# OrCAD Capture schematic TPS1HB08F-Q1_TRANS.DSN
size E; title: TPS1HB08F-Q1: 40-V, 8-mOhm Single-Channel Smart; rev: 1.0; note: Datasheet: SLVSE16C     EVM: NA; note: High-Side Switch
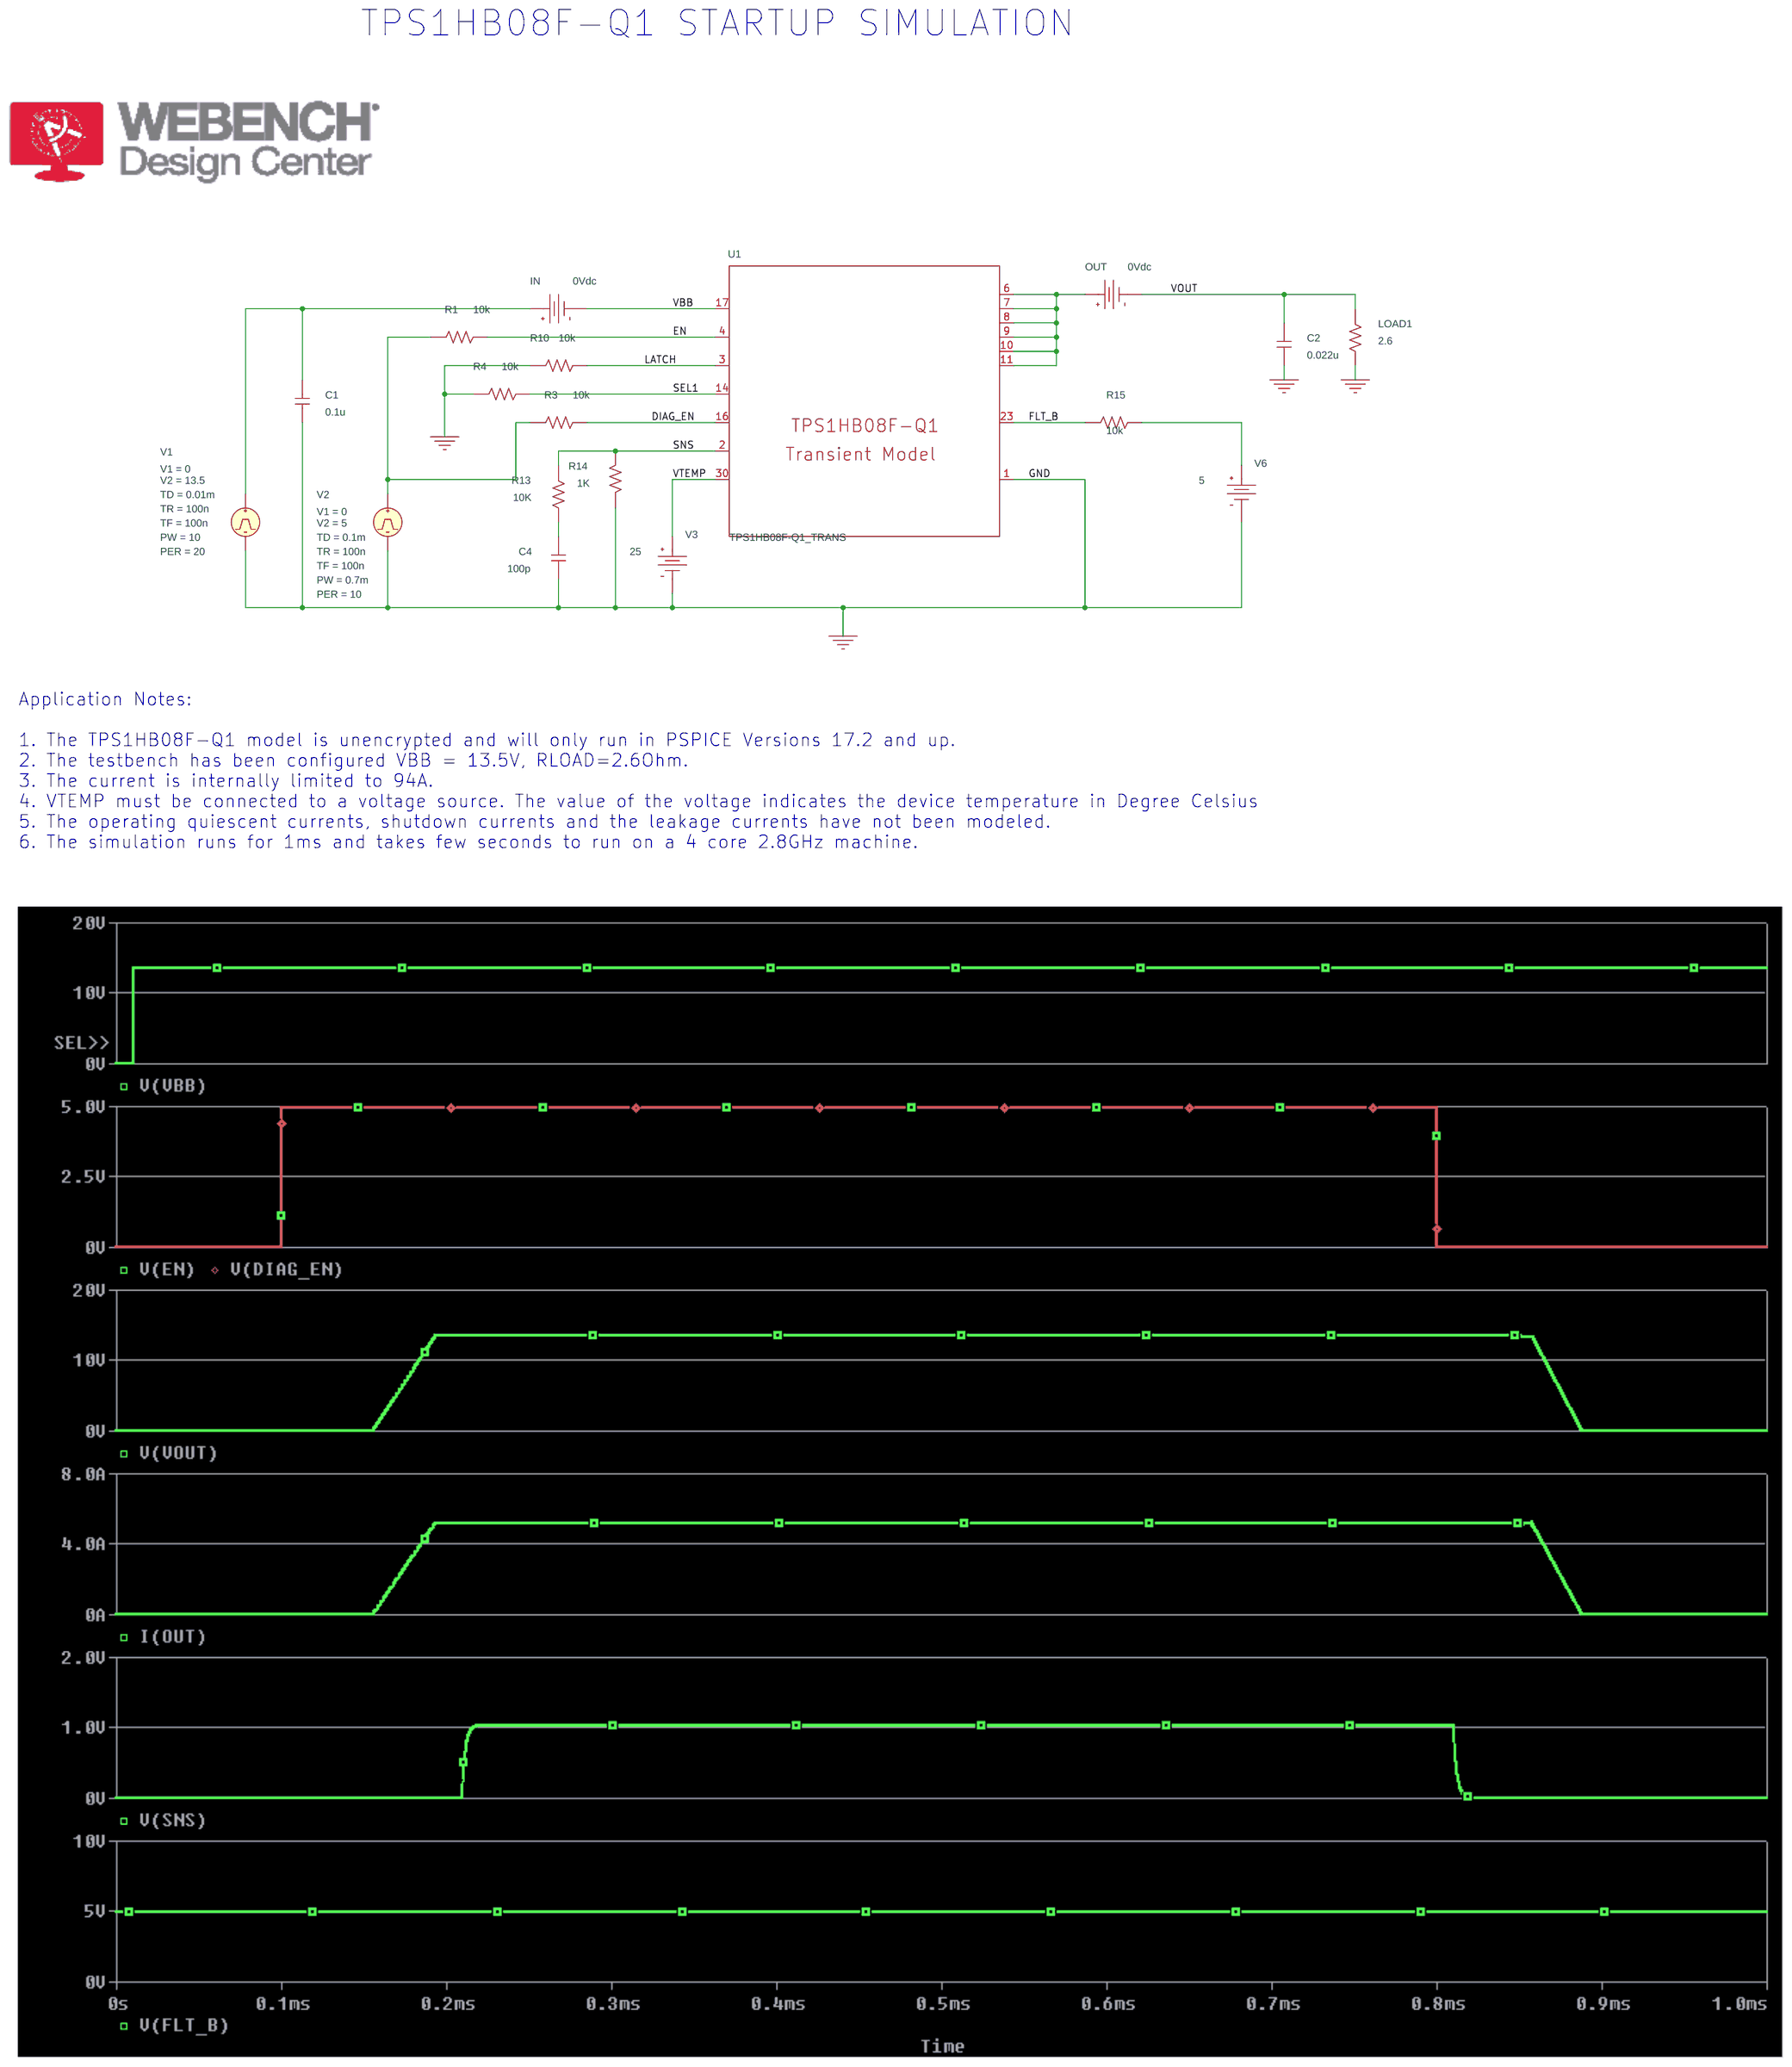
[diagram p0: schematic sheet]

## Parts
C1  0.1u  [RAD/CK05]
C2  0.022u  [RAD/CK05]
C4  100p  [RAD/CK05]
IN  VDC
LOAD1  2.6  [AX/RC05]
OUT  VDC
R1  10k  [AX/RC05]
R3  10k  [AX/RC05]
R4  10k  [AX/RC05]
R10  10k  [AX/RC05]
R13  10K  [AX/RC05]
R14  1K  [AX/RC05]
R15  10k  [AX/RC05]
U1  TPS1HB08F-Q1_TRANS  [PWP0016M_N]
V1  VPULSE
V2  VPULSE
V3  VDC
V6  VDC

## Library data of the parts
C1 C2 C4 = C
IN OUT = VDC: DC: 0Vdc
LOAD1 R1 R3 R4 R10 R13-R15 = R
U1 = TPS1HB08F-Q1_TRANS
V1 = VPULSE: PER: 20; PW: 10; TD: 0.01m; TF: 100n; TR: 100n; V1: 0; V2: 13.5
V2 = VPULSE: PER: 10; PW: 0.7m; TD: 0.1m; TF: 100n; TR: 100n; V1: 0; V2: 5
V3 = VDC: DC: 25
V6 = VDC: DC: 5

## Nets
0: C1.2 C2.2 C4.2 LOAD1.2 R4.1 R10.1 R14.1 U1.1(GND) V1.2(-) V2.2(-) V3.1(-) V6.1(-)
DIAG_EN: R3.2 U1.16(DIA_EN)
EN: R1.2 U1.4(EN)
FLT_B: R15.1 U1.23(FLT_B)
LATCH: R10.2 U1.3(LATCH)
SEL1: R4.2 U1.14(SEL1)
SNS: R13.1 R14.2 U1.2(SNS)
VBB: IN.1(-) U1.17(VBB)
VOUT: C2.1 LOAD1.1 OUT.1(-)
VTEMP: U1.30(VTEMP) V3.0(+)
N16778674: R15.2 V6.0(+)
N16779249: C1.1 IN.0(+) V1.1(+)
N16779878: R1.1 R3.1 V2.1(+)
N16780602: OUT.0(+) U1.6(VOUT_0) U1.7(VOUT_1) U1.8(VOUT_2) U1.9(VOUT_3) U1.10(VOUT_4) U1.11(VOUT_5)
N16781911: C4.1 R13.2

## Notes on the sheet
- TPS1HB08F-Q1 STARTUP SIMULATION
- Application Notes:
  1. The TPS1HB08F-Q1 model is unencrypted and will only run in PSPICE Versions 17.2 and up.
  2. The testbench has been configured VBB = 13.5V, RLOAD=2.6Ohm.
  3. The current is internally limited to 94A.
  4. VTEMP must be connected to a voltage source. The value of the voltage indicates the device temperature in Degree Celsius
  5. The operating quiescent currents, shutdown currents and the leakage currents have not been modeled.
  6. The simulation runs for 1ms and takes few seconds to run on a 4 core 2.8GHz machine.
